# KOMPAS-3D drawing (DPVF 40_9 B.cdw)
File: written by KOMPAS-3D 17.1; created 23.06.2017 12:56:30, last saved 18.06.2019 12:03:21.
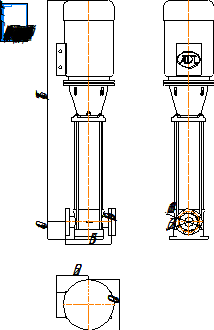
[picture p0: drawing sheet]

Sheet 1: A4, portrait

Title block, sheet 1: name: DPVF 40_9 B; material: Внимание! Данный продукт является объектом авторского права ООО «Торговый Дом АДЛ». / Запрещается изменение, копирование, распространение / (в том числе путем копирования на другие сайты и ресурсы в Интернете) / или любое иное использование информации и объектов без предварительного / согласия правообладателя (ООО «Торговый Дом АДЛ»).; scale: 1:1; sheets: 1; organisation: ООО "Торговый дом АДЛ"; sheet format: A4; stored path: C:\Клочков АВ\Насосы\DP PAMS\DPVF 40\Компас 2d\DPVF 40_9 B.cdw

Views: Спереди 1
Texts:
  Клочков АВ
  ООО АДЛ ГРУПП
Dimensions and other numbers on the sheet: 365; 250; 400; 209,6; 1741,5; 140; 168,1; 76,2; 1:1; 1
